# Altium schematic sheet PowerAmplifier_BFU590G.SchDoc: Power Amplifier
size A4; Author: Almela; Revision: 1.2; SheetNumber: 4; SheetTotal: 7
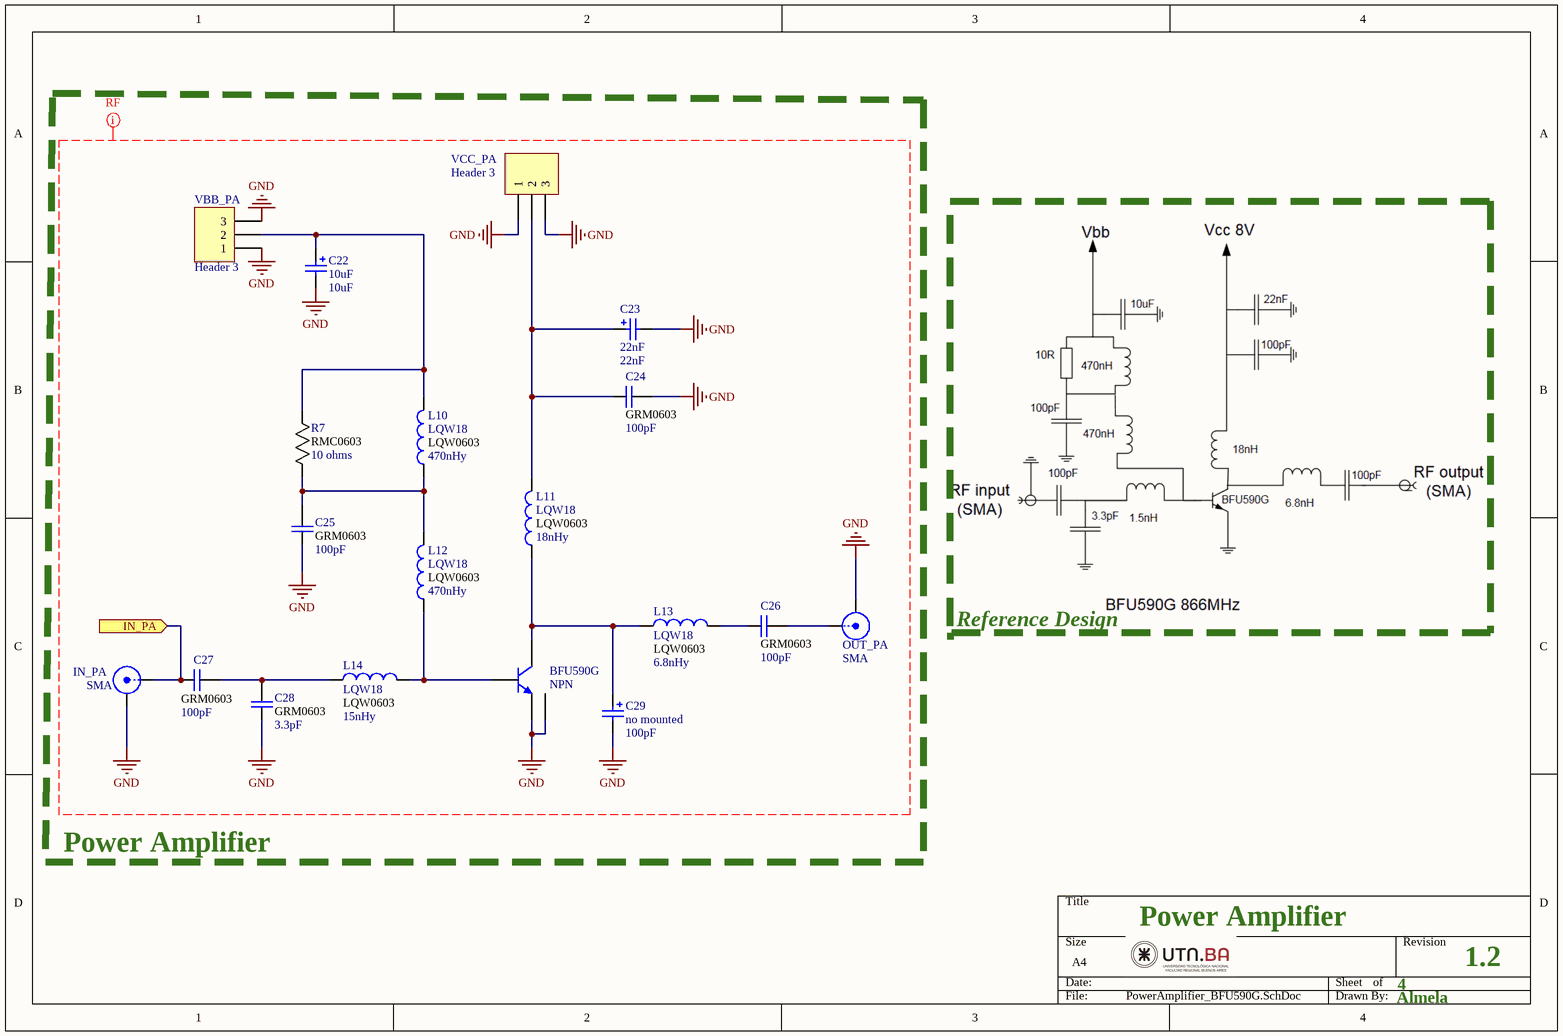
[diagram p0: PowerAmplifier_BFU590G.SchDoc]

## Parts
BFU590G  NPN  [SOT223_L]
C22  10uF  [6-0805_N]
C23  22nF  [6-0805_N]
C24  value 100pF  footprint: GRM0603  [CAPC1608X90N]  (hidden comment: Cap 0603)
C25  value 100pF  footprint: GRM0603  [CAPC1608X90N]  (hidden comment: Cap 0603)
C26  value 100pF  footprint: GRM0603  [CAPC1608X90N]  (hidden comment: Cap 0603)
C27  value 100pF  footprint: GRM0603  [CAPC1608X90N]  (hidden comment: Cap 0603)
C28  value 3.3pF  footprint: GRM0603  [CAPC1608X90N]  (hidden comment: Cap 0603)
C29  no mounted  value 100pF  [6-0805_N]
IN_PA  SMA  [SMA-142-0701-851]
L10  LQW18  value 470nHy  Parameter 1: LQW0603  [INDC1608X100N]
L11  LQW18  value 18nHy  Parameter 1: LQW0603  [INDC1608X100N]
L12  LQW18  value 470nHy  Parameter 1: LQW0603  [INDC1608X100N]
L13  LQW18  value 6.8nHy  Parameter 1: LQW0603  [INDC1608X100N]
L14  LQW18  value 15nHy  Parameter 1: LQW0603  [INDC1608X100N]
OUT_PA  SMA  [SMA-142-0701-851]
R7  value 10 ohms  footprint: RMC0603  [RESC1508X55N]  (hidden comment: Resistor)
VBB_PA  Header 3  [HDR1X3]
VCC_PA  Header 3  [HDR1X3]

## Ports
IN_PA (in)

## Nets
GND: BFU590G.1(E) BFU590G.3(E) C22.2 C23.2 C24.2 C25.1 C28.1 C29.2 IN_PA.2(Y) OUT_PA.2(Y) VBB_PA.1 VBB_PA.3 VCC_PA.1 VCC_PA.3
IN_PA: C27.1 IN_PA.1(X) ; port IN_PA
NetBFU590G_2: BFU590G.2(B) L12.1 L14.2
NetBFU590G_4: BFU590G.4(C) C29.1 L11.1 L13.1
NetC22_1: C22.1 L10.2 R7.2 VBB_PA.2
NetC23_1: C23.1 C24.1 L11.2 VCC_PA.2
NetC25_2: C25.2 L10.1 L12.2 R7.1
NetC26_1: C26.1 L13.2
NetC26_2: C26.2 OUT_PA.1(X)
NetC27_2: C27.2 C28.2 L14.1

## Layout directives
net class RF50R: GND

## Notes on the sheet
- Reference Design
- Power Amplifier

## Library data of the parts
BFU590G = BFU590G: NPN Bipolar Transistor
C22 = Cap Pol2_7: Polarized Capacitor (Axial)
C23 C29 = Cap Pol2_1: Polarized Capacitor (Axial)
C24-C28 = Cap: Capacitor GRM18 0603
IN_PA OUT_PA = SMA: SMA Straight Connector
L10-L14 = LQW18: Ind RF Chip Wirewound 18nH 5% 100MHz 40Q-Factor 550mA 0603 Paper T/R; MP: LQW18AN18NJ00D
R7 = Resistor: Resistor RMC0603; Mfr_Name: Stackpole International
VBB_PA VCC_PA = Header 3: Header, 3-Pin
